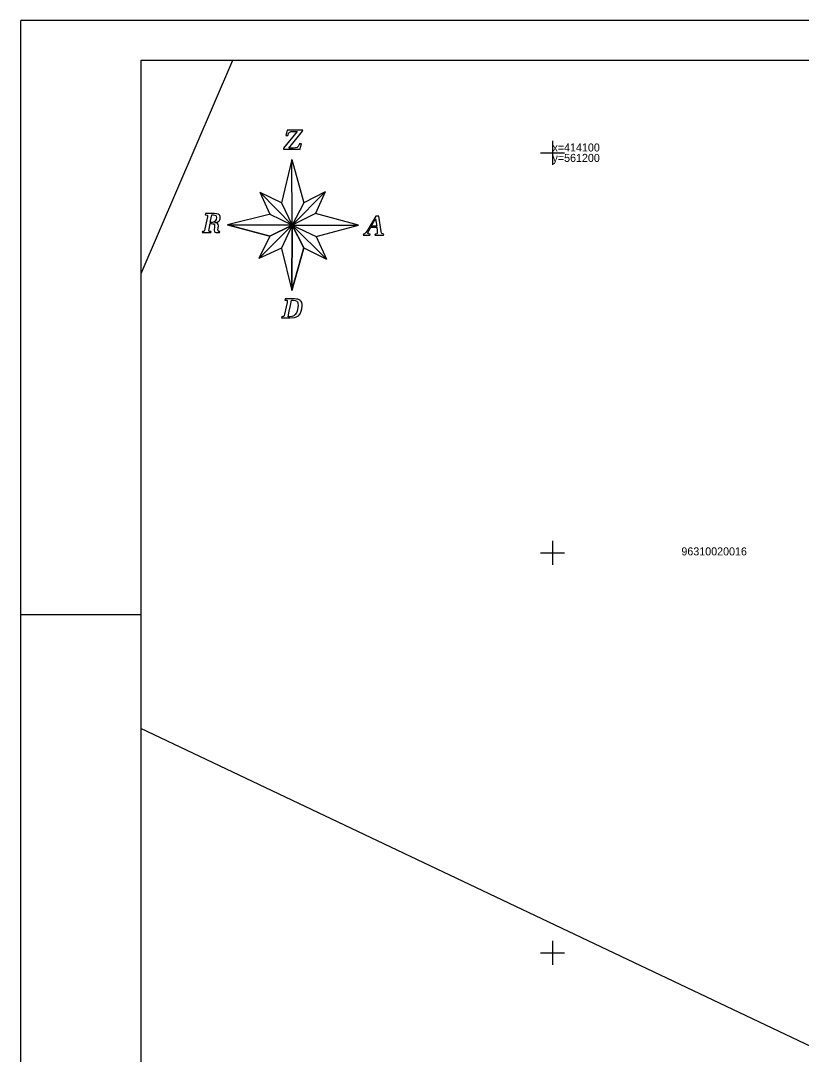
# Model space of a CAD drawing. Extents: x 561134 to 561329, y 413819 to 414116.
# Drawn here: x 561133.6 to 561231.1, y 413987.3 to 414116.5 of the extents above; entities that cross this region are included whole.
import ezdxf

# ---------------------------------------------------------------- set-up
doc = ezdxf.new("R2010")
doc.units = 0
for name, color, linetype in [('GEOD_ELEM_####_####_#', 7, 'Continuous'), ('GEOD_KORD_####_TKST_#', 7, 'Continuous'), ('RAMI_PLAN_####_TKST_#', 7, 'Continuous'), ('ROBZ_UZMR_####_####_#', 7, 'Continuous'), ('ROBZ_UZMR_####_TKST_#', 7, 'Continuous')]:
    doc.layers.add(name, color=color, linetype=linetype)

msp = doc.modelspace()

# ---------------------------------------------------------------- linework, layer by layer
at = {"layer": 'GEOD_ELEM_####_####_#'}
for p, q in [((561200, 414101.5), (561200, 414100)), ((561198.5, 414100), (561200, 414100)), ((561200, 414100), (561200, 414098.5)), ((561200, 414100), (561201.5, 414100)), ((561200, 414051.5), (561200, 414050)), ((561198.5, 414050), (561200, 414050)), ((561200, 414050), (561200, 414048.5)), ((561200, 414050), (561201.5, 414050)), ((561200, 414001.5), (561200, 414000)), ((561198.5, 414000), (561200, 414000)), ((561200, 414000), (561200, 413998.5)), ((561200, 414000), (561201.5, 414000))]:
    msp.add_line(p, q, dxfattribs=at)
at = {"layer": 'RAMI_PLAN_####_TKST_#'}
for p, q in [((561133.58, 413968), (561133.58, 414116.5)), ((561328.58, 414116.5), (561133.58, 414116.5)), ((561168.12, 414102.66), (561166.4, 414100.55)), ((561166.81, 414102.59), (561166.7, 414102.14)), ((561166.7, 414102.14), (561166.94, 414102.14)), ((561166.86, 414102.8), (561166.81, 414102.59)), ((561168.8, 414102.8), (561166.86, 414102.8)), ((561166.94, 414102.14), (561167.07, 414102.46)), ((561167.07, 414100.58), (561168.78, 414102.68)), ((561167.07, 414102.46), (561167.15, 414102.55)), ((561167.15, 414102.55), (561167.26, 414102.61)), ((561167.26, 414102.61), (561167.38, 414102.65)), ((561167.38, 414102.65), (561167.54, 414102.66)), ((561167.54, 414102.66), (561168.12, 414102.66)), ((561168.78, 414102.68), (561168.8, 414102.8)), ((561168.09, 414100.63), (561167.92, 414100.59)), ((561168.24, 414100.76), (561168.09, 414100.63)), ((561168.36, 414101.01), (561168.24, 414100.76)), ((561168.4, 414101.1), (561168.36, 414101.01)), ((561168.64, 414101.1), (561168.4, 414101.1)), ((561168.47, 414100.44), (561168.53, 414100.69)), ((561168.53, 414100.69), (561168.64, 414101.1)), ((561166.4, 414100.55), (561166.39, 414100.44)), ((561166.39, 414100.44), (561168.47, 414100.44)), ((561167.62, 414100.58), (561167.07, 414100.58)), ((561167.92, 414100.59), (561167.62, 414100.58)), ((561171.62, 414095.09), (561168.96, 414093.74)), ((561156.9, 414091.98), (561156.59, 414090.47)), ((561156.66, 414092.38), (561156.63, 414092.23)), ((561156.63, 414092.23), (561156.69, 414092.23)), ((561157.22, 414092.38), (561156.66, 414092.38)), ((561156.69, 414092.23), (561156.87, 414092.21)), ((561156.87, 414092.21), (561156.9, 414092.17)), ((561156.9, 414092.17), (561156.92, 414092.1)), ((561156.92, 414092.1), (561156.9, 414091.98)), ((561157.73, 414092.38), (561157.22, 414092.38)), ((561157.26, 414091.29), (561157.47, 414092.23)), ((561157.47, 414092.23), (561157.64, 414092.23)), ((561157.64, 414092.23), (561157.82, 414092.21)), ((561158.04, 414092.36), (561157.73, 414092.38)), ((561157.82, 414092.21), (561157.94, 414092.16)), ((561157.99, 414091.64), (561157.88, 414091.45)), ((561157.94, 414092.16), (561158.01, 414092.05)), ((561158.03, 414091.88), (561157.99, 414091.64)), ((561158.01, 414092.05), (561158.03, 414091.88)), ((561158.25, 414092.3), (561158.04, 414092.36)), ((561158.36, 414092.23), (561158.25, 414092.3)), ((561158.44, 414092.14), (561158.36, 414092.23)), ((561158.4, 414091.52), (561158.46, 414091.62)), ((561158.49, 414092.02), (561158.44, 414092.14)), ((561158.46, 414091.62), (561158.49, 414091.74)), ((561158.5, 414091.88), (561158.49, 414092.02)), ((561158.49, 414091.74), (561158.5, 414091.88)), ((561164.79, 414092.33), (561159.42, 414090.98)), ((561177.92, 414092.05), (561176.84, 414090.24)), ((561177.35, 414090.82), (561177.89, 414091.74)), ((561177.89, 414091.74), (561178.04, 414090.82)), ((561178.33, 414092.05), (561177.92, 414092.05)), ((561178.62, 414090.15), (561178.33, 414092.05)), ((561156.53, 414090.29), (561156.48, 414090.2)), ((561156.59, 414090.47), (561156.53, 414090.29)), ((561157.09, 414090.28), (561157.11, 414090.46)), ((561157.1, 414090.21), (561157.09, 414090.28)), ((561157.11, 414090.46), (561157.25, 414091.15)), ((561157.25, 414091.15), (561157.42, 414091.15)), ((561157.52, 414091.29), (561157.26, 414091.29)), ((561157.42, 414091.15), (561157.59, 414091.13)), ((561157.72, 414091.33), (561157.52, 414091.29)), ((561157.59, 414091.13), (561157.7, 414091.1)), ((561157.7, 414091.1), (561157.77, 414091)), ((561157.88, 414091.45), (561157.72, 414091.33)), ((561157.77, 414090.61), (561157.75, 414090.45)), ((561157.75, 414090.45), (561157.75, 414090.32)), ((561157.75, 414090.32), (561157.77, 414090.17)), ((561157.77, 414091), (561157.79, 414090.85)), ((561157.79, 414090.74), (561157.77, 414090.61)), ((561157.79, 414090.85), (561157.79, 414090.74)), ((561157.87, 414091.26), (561158.12, 414091.33)), ((561157.87, 414091.24), (561157.87, 414091.26)), ((561158.04, 414091.22), (561157.87, 414091.24)), ((561158.17, 414091.15), (561158.04, 414091.22)), ((561158.12, 414091.33), (561158.32, 414091.43)), ((561158.24, 414091.03), (561158.17, 414091.15)), ((561158.22, 414090.34), (561158.25, 414090.58)), ((561158.23, 414090.25), (561158.22, 414090.34)), ((561158.27, 414090.85), (561158.24, 414091.03)), ((561158.25, 414090.58), (561158.27, 414090.85)), ((561158.32, 414091.43), (561158.4, 414091.52)), ((561159.42, 414090.98), (561167.5, 414090.93)), ((561164.68, 414089.57), (561159.42, 414090.98)), ((561163.33, 414086.76), (561167.5, 414090.93)), ((561167.5, 414090.93), (561164.68, 414089.57)), ((561167.5, 414090.93), (561166.14, 414088.07)), ((561167.45, 414082.76), (561167.5, 414090.93)), ((561167.5, 414090.93), (561168.96, 414088.12)), ((561177, 414090.14), (561177.1, 414090.3)), ((561177.1, 414090.3), (561177.32, 414090.68)), ((561177.32, 414090.68), (561178.04, 414090.68)), ((561178.04, 414090.82), (561177.35, 414090.82)), ((561178.04, 414090.68), (561178.11, 414090.22)), ((561156.27, 414090.15), (561156.24, 414090.01)), ((561156.24, 414090.01), (561156.78, 414090.01)), ((561156.41, 414090.16), (561156.27, 414090.15)), ((561156.48, 414090.2), (561156.41, 414090.16)), ((561156.78, 414090.01), (561157.34, 414090.01)), ((561157.14, 414090.17), (561157.1, 414090.21)), ((561157.37, 414090.15), (561157.14, 414090.17)), ((561157.34, 414090.01), (561157.37, 414090.15)), ((561157.77, 414090.17), (561157.83, 414090.08)), ((561157.83, 414090.08), (561157.94, 414090.03)), ((561157.94, 414090.03), (561158.09, 414090.01)), ((561158.09, 414090.01), (561158.43, 414090.01)), ((561158.27, 414090.2), (561158.23, 414090.25)), ((561158.34, 414090.16), (561158.27, 414090.2)), ((561158.46, 414090.15), (561158.34, 414090.16)), ((561158.43, 414090.01), (561158.46, 414090.15)), ((561164.68, 414089.57), (561163.33, 414086.76)), ((561176.38, 414089.83), (561176.35, 414089.69)), ((561176.35, 414089.69), (561176.78, 414089.69)), ((561176.54, 414089.86), (561176.38, 414089.83)), ((561176.66, 414089.97), (561176.54, 414089.86)), ((561176.84, 414090.24), (561176.66, 414089.97)), ((561176.78, 414089.69), (561177.2, 414089.69)), ((561176.94, 414089.95), (561177, 414090.14)), ((561176.95, 414089.9), (561176.94, 414089.95)), ((561177, 414089.86), (561176.95, 414089.9)), ((561177.23, 414089.83), (561177, 414089.86)), ((561177.2, 414089.69), (561177.23, 414089.83)), ((561177.85, 414089.83), (561177.82, 414089.69)), ((561177.82, 414089.69), (561178.36, 414089.69)), ((561178.04, 414089.84), (561177.85, 414089.83)), ((561178.1, 414089.89), (561178.04, 414089.84)), ((561178.12, 414089.97), (561178.1, 414089.89)), ((561178.11, 414090.22), (561178.12, 414090.08)), ((561178.12, 414090.08), (561178.12, 414089.97)), ((561178.36, 414089.69), (561178.91, 414089.69)), ((561178.66, 414090), (561178.62, 414090.15)), ((561178.7, 414089.92), (561178.66, 414090)), ((561178.79, 414089.85), (561178.7, 414089.92)), ((561178.94, 414089.83), (561178.79, 414089.85)), ((561178.91, 414089.69), (561178.94, 414089.83)), ((561166.14, 414088.07), (561163.33, 414086.76)), ((561166.14, 414088.01), (561167.45, 414082.76)), ((561168.96, 414088.12), (561167.45, 414082.76)), ((561166.85, 414081.27), (561166.52, 414079.81)), ((561166.62, 414081.72), (561166.59, 414081.58)), ((561166.59, 414081.58), (561166.82, 414081.56)), ((561167.16, 414081.72), (561166.62, 414081.72)), ((561166.82, 414081.56), (561166.86, 414081.52)), ((561166.87, 414081.37), (561166.85, 414081.27)), ((561166.86, 414081.52), (561166.87, 414081.45)), ((561166.87, 414081.45), (561166.87, 414081.37)), ((561167.78, 414081.72), (561167.16, 414081.72)), ((561167.27, 414080.89), (561167.42, 414081.58)), ((561167.42, 414081.58), (561167.6, 414081.58)), ((561167.6, 414081.58), (561167.88, 414081.55)), ((561168.01, 414081.71), (561167.78, 414081.72)), ((561167.88, 414081.55), (561168.07, 414081.44)), ((561168.21, 414081.68), (561168.01, 414081.71)), ((561168.07, 414081.44), (561168.14, 414081.35)), ((561168.14, 414081.35), (561168.19, 414081.25)), ((561168.19, 414081.25), (561168.21, 414081.12)), ((561168.37, 414081.62), (561168.21, 414081.68)), ((561168.5, 414081.54), (561168.37, 414081.62)), ((561168.61, 414081.42), (561168.5, 414081.54)), ((561168.68, 414081.27), (561168.61, 414081.42)), ((561168.73, 414081.07), (561168.68, 414081.27)), ((561166.97, 414079.5), (561167.11, 414080.2)), ((561167.11, 414080.2), (561167.27, 414080.89)), ((561168.01, 414079.97), (561167.86, 414079.76)), ((561168.1, 414080.18), (561168.01, 414079.97)), ((561168.17, 414080.41), (561168.1, 414080.18)), ((561168.21, 414080.67), (561168.17, 414080.41)), ((561168.21, 414081.12), (561168.22, 414080.96)), ((561168.22, 414080.96), (561168.21, 414080.67)), ((561168.47, 414079.87), (561168.63, 414080.18)), ((561168.63, 414080.18), (561168.71, 414080.5)), ((561168.71, 414080.5), (561168.74, 414080.85)), ((561168.74, 414080.85), (561168.73, 414081.07)), ((561166.18, 414079.5), (561166.15, 414079.36)), ((561166.15, 414079.36), (561166.71, 414079.36)), ((561166.34, 414079.51), (561166.18, 414079.5)), ((561166.43, 414079.55), (561166.34, 414079.51)), ((561166.48, 414079.64), (561166.43, 414079.55)), ((561166.52, 414079.81), (561166.48, 414079.64)), ((561166.71, 414079.36), (561167.23, 414079.36)), ((561167.21, 414079.5), (561166.97, 414079.5)), ((561167.46, 414079.53), (561167.21, 414079.5)), ((561167.23, 414079.36), (561167.78, 414079.39)), ((561167.68, 414079.62), (561167.46, 414079.53)), ((561167.86, 414079.76), (561167.68, 414079.62)), ((561167.78, 414079.39), (561168.04, 414079.48)), ((561168.04, 414079.48), (561168.26, 414079.63)), ((561168.26, 414079.63), (561168.47, 414079.87)), ((561148.58, 414042.25), (561133.58, 414042.25))]:
    msp.add_line(p, q, dxfattribs=at)
for points in [[(561148.58, 414111.5), (561148.58, 413824.5), (561323.58, 413824.5), (561323.58, 414111.5)], [(561167.45, 414099.15), (561166.14, 414093.74), (561167.5, 414090.93)], [(561175.79, 414090.93), (561170.42, 414092.39), (561167.5, 414090.93)], [(561159.42, 414090.98), (561164.68, 414089.57), (561167.5, 414090.93)], [(561167.5, 414090.93), (561167.45, 414082.76), (561168.96, 414088.12)]]:
    msp.add_lwpolyline(points, close=True, dxfattribs=at)
for points in [[(561167.45, 414099.15), (561168.96, 414093.74), (561167.5, 414090.93), (561167.45, 414099.15), (561166.14, 414093.74), (561167.5, 414090.93)], [(561166.14, 414093.74), (561163.48, 414095.03), (561167.5, 414090.93), (561164.74, 414092.28), (561163.48, 414095.03)], [(561167.5, 414090.93), (561171.62, 414095.09), (561170.42, 414092.39)], [(561170.47, 414089.52), (561175.79, 414090.93), (561170.42, 414092.39), (561167.5, 414090.93), (561175.79, 414090.93)], [(561168.96, 414088.12), (561171.77, 414086.71), (561167.5, 414090.93), (561170.47, 414089.52), (561171.77, 414086.71)]]:
    msp.add_lwpolyline(points, dxfattribs=at)
at = {"layer": 'ROBZ_UZMR_####_####_#'}
for p, q in [((561160.03, 414111.5), (561148.58, 414084.85)), ((561296.51, 413957.82), (561148.58, 414028.03))]:
    msp.add_line(p, q, dxfattribs=at)

# ---------------------------------------------------------------- texts
at = {"layer": 'GEOD_KORD_####_TKST_#'}
for s, p in [('x=414100', (561200, 414100.15)), ('y=561200', (561200, 414098.85))]:
    msp.add_text(s, height=1, dxfattribs=at).set_placement(p)
at = {"layer": 'ROBZ_UZMR_####_TKST_#'}
msp.add_text('96310020016', height=1, dxfattribs=at).set_placement((561216.1, 414049.68))

doc.saveas('drawing.dxf')
